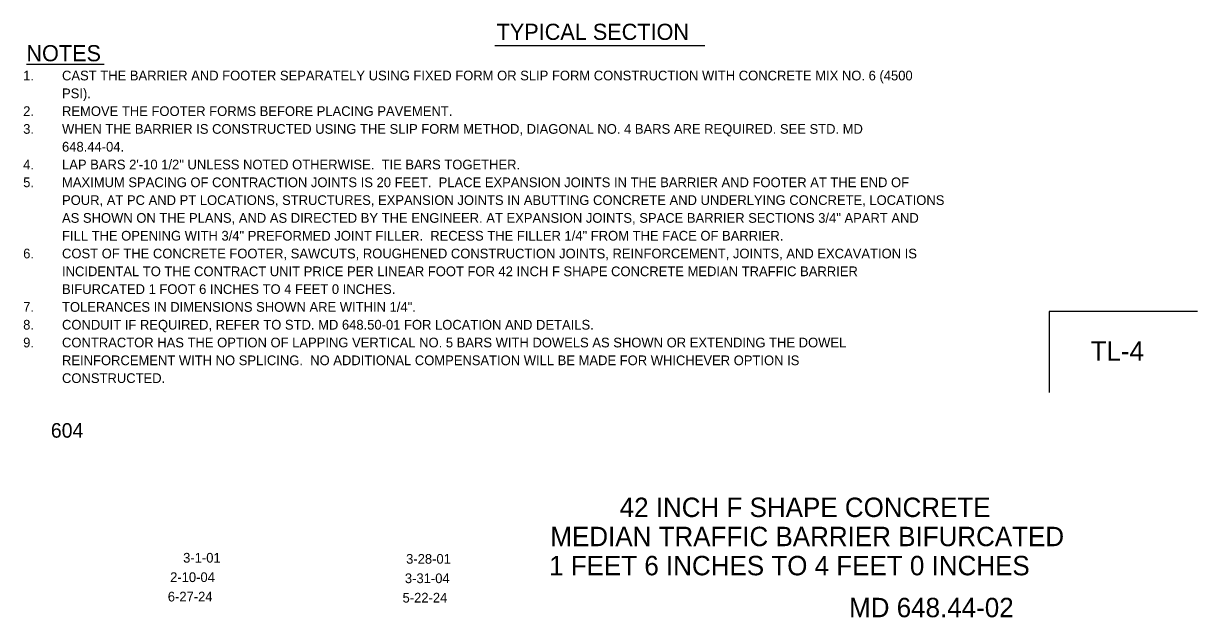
# Model space of a CAD drawing. Extents: x -26.5 to -19.2, y -3.6 to 6.6.
# Drawn here: x -26.46 to -19.21, y -3.62 to 0.05 of the extents above; entities that cross this region are included whole.
import ezdxf

# ---------------------------------------------------------------- set-up
doc = ezdxf.new("R2010")
doc.units = 0
for name, color, linetype in [('Level 1', 7, 'Continuous'), ('Level 12', 7, 'Continuous'), ('Level 13', 7, 'Continuous'), ('TTLB-TEXT', 7, 'Continuous')]:
    doc.layers.add(name, color=color, linetype=linetype)

msp = doc.modelspace()

# ---------------------------------------------------------------- linework, layer by layer
at = {"layer": 'Level 1'}
for p, q in [((-19.2061, -1.7326), (-20.1228, -1.7326)), ((-20.1228, -1.7326), (-20.1228, -2.2326))]:
    msp.add_line(p, q, dxfattribs=at)
at = {"layer": 'Level 12'}
msp.add_line((-23.5481, -0.0892), (-22.2512, -0.0892), dxfattribs=at)
at = {"layer": 'Level 13'}
msp.add_line((-26.4422, -0.2036), (-25.9619, -0.2036), dxfattribs=at)

# ---------------------------------------------------------------- texts
at = {"layer": 'Level 12'}
msp.add_text('TYPICAL SECTION', height=0.1, dxfattribs=at).set_placement((-23.5369, -0.0545))
at = {"layer": 'Level 13'}
for s, height, p in [('NOTES', 0.1, (-26.4421, -0.1866)), ('1.', 0.06, (-26.462, -0.3047)), ('CAST THE BARRIER AND FOOTER SEPARATELY USING FIXED FORM OR SLIP FORM CONSTRUCTION WITH CONCRETE MIX NO. 6 (4500 ', 0.06, (-26.222, -0.3047)), ('PSI).', 0.06, (-26.222, -0.4147)), ('2.', 0.06, (-26.462, -0.5247)), ('REMOVE THE FOOTER FORMS BEFORE PLACING PAVEMENT.', 0.06, (-26.222, -0.5247)), ('3.', 0.06, (-26.462, -0.6347)), ('WHEN THE BARRIER IS CONSTRUCTED USING THE SLIP FORM METHOD, DIAGONAL NO. 4 BARS ARE REQUIRED. SEE STD. MD ', 0.06, (-26.222, -0.6347)), ('648.44-04.', 0.06, (-26.222, -0.7447)), ('4.', 0.06, (-26.462, -0.8547)), ('LAP BARS 2\'-10 1/2" UNLESS NOTED OTHERWISE.  TIE BARS TOGETHER.', 0.06, (-26.222, -0.8547)), ('5.', 0.06, (-26.462, -0.9647)), ('MAXIMUM SPACING OF CONTRACTION JOINTS IS 20 FEET.  PLACE EXPANSION JOINTS IN THE BARRIER AND FOOTER AT THE END OF ', 0.06, (-26.222, -0.9647)), ('POUR, AT PC AND PT LOCATIONS, STRUCTURES, EXPANSION JOINTS IN ABUTTING CONCRETE AND UNDERLYING CONCRETE, LOCATIONS ', 0.06, (-26.222, -1.0747)), ('AS SHOWN ON THE PLANS, AND AS DIRECTED BY THE ENGINEER. AT EXPANSION JOINTS, SPACE BARRIER SECTIONS 3/4" APART AND ', 0.06, (-26.222, -1.1847)), ('FILL THE OPENING WITH 3/4" PREFORMED JOINT FILLER.  RECESS THE FILLER 1/4" FROM THE FACE OF BARRIER.', 0.06, (-26.222, -1.2947)), ('6.', 0.06, (-26.462, -1.4047)), ('COST OF THE CONCRETE FOOTER, SAWCUTS, ROUGHENED CONSTRUCTION JOINTS, REINFORCEMENT, JOINTS, AND EXCAVATION IS ', 0.06, (-26.222, -1.4047)), ('INCIDENTAL TO THE CONTRACT UNIT PRICE PER LINEAR FOOT FOR 42 INCH F SHAPE CONCRETE MEDIAN TRAFFIC BARRIER ', 0.06, (-26.222, -1.5147)), ('BIFURCATED 1 FOOT 6 INCHES TO 4 FEET 0 INCHES.', 0.06, (-26.222, -1.6247)), ('7.', 0.06, (-26.462, -1.7347)), ('TOLERANCES IN DIMENSIONS SHOWN ARE WITHIN 1/4".', 0.06, (-26.222, -1.7347)), ('8.', 0.06, (-26.462, -1.8447)), ('CONDUIT IF REQUIRED, REFER TO STD. MD 648.50-01 FOR LOCATION AND DETAILS.', 0.06, (-26.222, -1.8447)), ('9.', 0.06, (-26.462, -1.9547)), ('CONTRACTOR HAS THE OPTION OF LAPPING VERTICAL NO. 5 BARS WITH DOWELS AS SHOWN OR EXTENDING THE DOWEL ', 0.06, (-26.222, -1.9547)), ('REINFORCEMENT WITH NO SPLICING.  NO ADDITIONAL COMPENSATION WILL BE MADE FOR WHICHEVER OPTION IS ', 0.06, (-26.222, -2.0647)), ('CONSTRUCTED.', 0.06, (-26.222, -2.1747)), ('604', 0.09001, (-26.291, -2.5127)), ('42 INCH F SHAPE CONCRETE', 0.120019, (-22.7765, -3.0032)), ('MEDIAN TRAFFIC BARRIER BIFURCATED', 0.120019, (-23.2048, -3.1832)), ('3-1-01', 0.06, (-25.4736, -3.2848)), ('3-28-01', 0.06, (-24.0959, -3.2916)), ('1 FEET 6 INCHES TO 4 FEET 0 INCHES', 0.120019, (-23.2127, -3.3632)), ('2-10-04', 0.06, (-25.554, -3.4048)), ('3-31-04', 0.06, (-24.1035, -3.4116)), ('6-27-24', 0.06, (-25.5685, -3.5248)), ('5-22-24', 0.06, (-24.118, -3.5316)), ('MD 648.44-02', 0.12, (-21.3589, -3.6224))]:
    msp.add_text(s, height=height, dxfattribs=at).set_placement(p)
at = {"layer": 'TTLB-TEXT'}
msp.add_text('TL-4', height=0.12, dxfattribs=at).set_placement((-19.8667, -2.0369))

doc.saveas('drawing.dxf')
